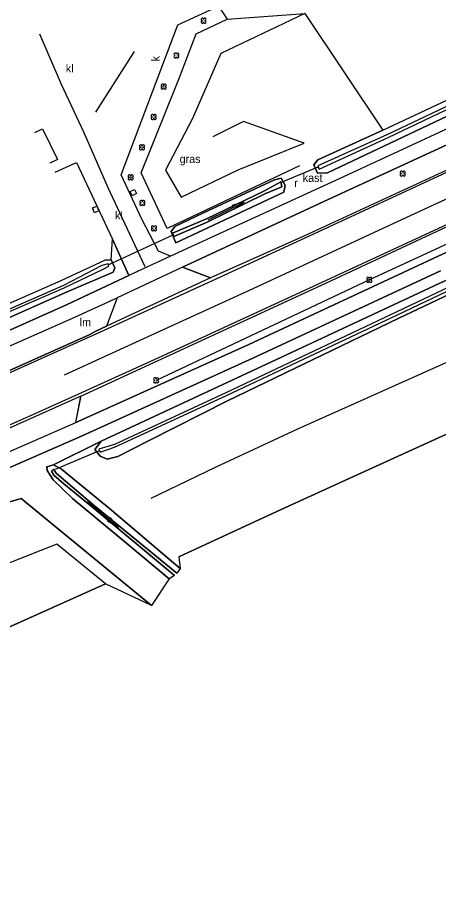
# Model space of a CAD drawing. Extents: x 154825 to 158680, y 370717 to 378075.
# Drawn here: x 157115 to 157167.5, y 372493.5 to 372604 of the extents above; entities that cross this region are included whole.
import ezdxf

# ---------------------------------------------------------------- set-up
doc = ezdxf.new("R2010")
doc.units = 0
for name, color, linetype in [('boom', 7, 'Continuous'), ('breuklijn', 7, 'Continuous'), ('cultuurscheiding', 7, 'Continuous'), ('deelstreep(3-9)', 7, 'Continuous'), ('duiker lijn', 7, 'Continuous'), ('grazige vegetatie(vs)', 7, 'Continuous'), ('hoogteverschillijn', 7, 'Continuous'), ('insteek sloot', 7, 'Continuous'), ('kantstreep', 7, 'Continuous'), ('kast_huis punt', 7, 'Continuous'), ('klinkerverharding(vs)', 7, 'Continuous'), ('kolk', 7, 'Continuous'), ('maaiveldlijn algemeen - gesloten verharding', 7, 'Continuous'), ('maaiveldlijn algemeen - muur', 7, 'Continuous'), ('maaiveldlijn algemeen - open verharding', 7, 'Continuous'), ('maaiveldlijn algemeen - verharding algemeen', 7, 'Continuous'), ('raster - hek', 7, 'Continuous'), ('rioolput(z_inl)', 7, 'Continuous'), ('Sloot bodem', 7, 'Continuous'), ('stroomrichting  watergangen', 7, 'Continuous'), ('verlichtingsobject', 7, 'Continuous'), ('vlak_Grasland', 7, 'Continuous'), ('vlak_Grazige_vegetatie', 7, 'Continuous')]:
    doc.layers.add(name, color=color, linetype=linetype)

msp = doc.modelspace()

# ---------------------------------------------------------------- linework, layer by layer
at = {"layer": 'boom'}
msp.add_lwpolyline([(157213.98, 372596.85), (157185.75, 372583.62), (157158.89, 372571.23), (157132.29, 372558.67)], dxfattribs=at)
for centre in [(157138.2, 372603.6), (157134.82, 372599.25), (157133.23, 372595.37), (157131.99, 372591.57), (157130.53, 372587.79), (157163.06, 372584.5), (157129.11, 372584.04), (157130.58, 372580.84), (157132.01, 372577.65), (157158.89, 372571.23), (157132.29, 372558.67)]:
    msp.add_circle(centre, 0.006, dxfattribs=at)
for centre, start, end in [((157138.05, 372603.76), 357.075, 272.925), ((157138.05, 372603.44), 87.075, 2.925), ((157138.36, 372603.76), 267.075, 182.925), ((157138.36, 372603.44), 177.075, 92.925), ((157134.67, 372599.41), 357.075, 272.925), ((157134.67, 372599.1), 87.075, 2.925), ((157134.98, 372599.41), 267.075, 182.925), ((157134.98, 372599.1), 177.075, 92.925), ((157133.07, 372595.53), 357.075, 272.925), ((157133.39, 372595.53), 267.075, 182.925), ((157133.07, 372595.22), 87.075, 2.925), ((157133.39, 372595.22), 177.075, 92.925), ((157131.83, 372591.73), 357.075, 272.925), ((157131.83, 372591.41), 87.075, 2.925), ((157132.15, 372591.73), 267.075, 182.925), ((157132.15, 372591.41), 177.075, 92.925), ((157130.37, 372587.95), 357.075, 272.925), ((157130.37, 372587.63), 87.075, 2.925), ((157130.69, 372587.95), 267.075, 182.925), ((157130.69, 372587.63), 177.075, 92.925), ((157162.9, 372584.66), 357.075, 272.925), ((157162.9, 372584.35), 87.075, 2.925), ((157163.22, 372584.66), 267.075, 182.925), ((157163.22, 372584.35), 177.075, 92.925), ((157128.95, 372584.2), 357.075, 272.925), ((157128.95, 372583.88), 87.075, 2.925), ((157129.27, 372584.2), 267.075, 182.925), ((157129.27, 372583.88), 177.075, 92.925), ((157130.42, 372581), 357.075, 272.925), ((157130.74, 372581), 267.075, 182.925), ((157130.42, 372580.69), 87.075, 2.925), ((157130.74, 372580.69), 177.075, 92.925), ((157131.85, 372577.81), 357.075, 272.925), ((157132.17, 372577.81), 267.075, 182.925), ((157131.85, 372577.5), 87.075, 2.925), ((157132.17, 372577.5), 177.075, 92.925), ((157158.73, 372571.39), 357.075, 272.925), ((157158.73, 372571.07), 87.075, 2.925), ((157159.04, 372571.39), 267.075, 182.925), ((157159.04, 372571.07), 177.075, 92.925), ((157132.13, 372558.83), 357.075, 272.925), ((157132.45, 372558.83), 267.075, 182.925), ((157132.13, 372558.51), 87.075, 2.925), ((157132.45, 372558.51), 177.075, 92.925)]:
    msp.add_arc(centre, 0.158, start, end, dxfattribs=at)
at = {"layer": 'breuklijn'}
for points in [[(157150.85, 372604.52), (157140.35, 372599.51), (157136.84, 372591.39), (157133.44, 372584.94), (157135.43, 372581.56), (157142.54, 372584.96), (157150.75, 372588.29), (157143.18, 372591.01), (157139.36, 372589.08)], [(157130.9, 372572.86), (157129, 372576.93), (157126.3, 372582.74), (157123.3, 372589.58), (157120.49, 372595.62), (157117.77, 372601.91)], [(157124.77, 372592.16), (157129.61, 372599.76)]]:
    msp.add_lwpolyline(points, dxfattribs=at)
at = {"layer": 'cultuurscheiding'}
msp.add_lwpolyline([(157119.47, 372548.1), (157125.41, 372551.06)], dxfattribs=at)
at = {"layer": 'deelstreep(3-9)'}
msp.add_lwpolyline([(157308.93, 372646.58), (157285.67, 372635.73), (157262.56, 372625), (157240.8, 372614.9), (157229.89, 372609.83), (157208.16, 372599.73), (157197.28, 372594.69), (157176.47, 372584.99), (157165.79, 372580.07), (157144.37, 372570.1), (157131.72, 372564.33), (157120.8, 372559.34)], dxfattribs=at)
at = {"layer": 'duiker lijn'}
for points in [[(157152.48, 372585.32), (157147.88, 372583.4)], [(157126.32, 372573.1), (157134.4, 372576.86)], [(157125.11, 372549.83), (157119.7, 372547.53)]]:
    msp.add_lwpolyline(points, dxfattribs=at)
at = {"layer": 'hoogteverschillijn'}
for points in [[(157135.14, 372536.64), (157147.33, 372542.3), (157157.39, 372546.88), (157174.01, 372554.44), (157182.06, 372557.76), (157199.41, 372565.5), (157207.14, 372569.14), (157217.33, 372573.59), (157225.17, 372577.25), (157220.34, 372585.21), (157210.16, 372580.28), (157199.1, 372574.84), (157186.14, 372569.77), (157176.77, 372565.02), (157169.17, 372561.19), (157149.94, 372552.57), (157139.65, 372547.77), (157131.61, 372543.92)], [(157026.21, 372507.77), (157038.05, 372493.47), (157053.84, 372500.41), (157064.32, 372505.29), (157082.04, 372513.73), (157099.19, 372521.06), (157114.22, 372527.96), (157125.97, 372533.26), (157119.9, 372538.21), (157106.1, 372532.74), (157095.12, 372527.24), (157084.64, 372522.61), (157073.6, 372517.88), (157061.99, 372513.42), (157050.38, 372508.13), (157038.81, 372503.28)]]:
    msp.add_lwpolyline(points, dxfattribs=at)
at = {"layer": 'insteek sloot'}
for points in [[(157185.03, 372601.76), (157185.99, 372601.72), (157186.54, 372600.97), (157186.51, 372600.12), (157184.6, 372599.14), (157168.61, 372591.68), (157153.67, 372584.61), (157152.41, 372584.57), (157151.95, 372585.58), (157152.47, 372586.22), (157160.56, 372589.94), (157178.13, 372598.16), (157185.03, 372601.76)], [(157125.41, 372551.06), (157144.82, 372560.12), (157168.23, 372571.06), (157192.15, 372582.14), (157214.33, 372592.42), (157231.51, 372600.35)], [(157229.49, 372575.59), (157223.27, 372585.02), (157219.29, 372591.66), (157218.52, 372591.88), (157205.82, 372586.39), (157183.29, 372576.28), (157162.59, 372566.44), (157141.18, 372556.1), (157131.42, 372551.16), (157127.51, 372549.15), (157126.18, 372548.81), (157125.29, 372549.21), (157124.66, 372550.05), (157125.41, 372551.06)], [(157147.04, 372583.73), (157147.87, 372583.94), (157148.37, 372583.02), (157148.23, 372582.18), (157134.76, 372575.84), (157134.63, 372576.16), (157134.15, 372577.27), (157134.64, 372577.88), (157138.1, 372579.57), (157147.04, 372583.73)], [(157108.06, 372566.2), (157109.34, 372566.26), (157120.45, 372571.14), (157125.98, 372573.72), (157126.66, 372573.71), (157127.14, 372572.72), (157126.93, 372572.17), (157120.88, 372569.62), (157108.26, 372564), (157096.05, 372558.59), (157082.53, 372552.97), (157070.93, 372548.12), (157053.32, 372541.26), (157038.38, 372535.36), (157020.77, 372528.28), (157013.25, 372525.44), (157009.25, 372524.08)], [(157133.93, 372533.88), (157128.63, 372538.31), (157121.87, 372543.93), (157119.44, 372546.24), (157118.68, 372547.42), (157118.65, 372547.86), (157119.47, 372548.1)], [(157119.47, 372548.1), (157120.5, 372547.57), (157126.45, 372542.68), (157135.3, 372535.16)]]:
    msp.add_lwpolyline(points, dxfattribs=at)
at = {"layer": 'kantstreep'}
for points in [[(157311.2, 372650.93), (157292.95, 372642.43), (157267.24, 372630.47), (157245.28, 372620.26), (157218.06, 372607.61), (157194.71, 372596.77), (157169.7, 372585.19), (157150.86, 372576.45), (157139.72, 372571.31), (157125.21, 372564.64), (157109.64, 372557.65), (157098.21, 372552.78), (157087.26, 372548.23), (157074.29, 372542.96), (157049.86, 372533.16), (157026.89, 372524.04), (157012.16, 372518.48), (156991.58, 372511.62)], [(157175.88, 372581.53), (157152.95, 372570.91), (157132.6, 372561.49), (157122.61, 372556.94), (157115.96, 372553.95), (157107.38, 372550.18), (157099.77, 372546.99), (157087.24, 372541.81), (157074.56, 372536.7), (157059.91, 372530.81), (157042.11, 372523.71), (157012.96, 372512.06), (157003.79, 372508.51)]]:
    msp.add_lwpolyline(points, dxfattribs=at)
at = {"layer": 'maaiveldlijn algemeen - gesloten verharding'}
for points in [[(157322.19, 372661.35), (157315.02, 372658), (157308.87, 372655.13), (157283.28, 372643.29), (157259.58, 372632.3), (157235.97, 372621.56), (157212.56, 372610.51), (157191.51, 372600.67), (157169.85, 372590.67), (157155.14, 372583.86), (157134.07, 372574.17)], [(157122.91, 372556.7), (157132.56, 372561.17), (157152.93, 372570.58), (157176.01, 372581.34), (157200.28, 372592.63), (157225.35, 372604.23), (157226.76, 372604.76), (157235.03, 372608.61)], [(157110.82, 372548.4), (157122.28, 372553.42), (157143.85, 372563.14), (157166.86, 372573.91), (157191.27, 372585.24), (157213.36, 372595.47), (157229.94, 372603.18)], [(157188.29, 372597.29), (157170.71, 372589.1), (157153.74, 372581.26), (157135.57, 372572.82)], [(157188.24, 372594.03), (157169.63, 372585.45), (157150.71, 372576.68), (157139.08, 372571.47)], [(157134.07, 372574.17), (157128.9, 372571.78)], [(157167.76, 372572.35), (157144.36, 372561.46), (157123.04, 372551.73), (157111.7, 372546.79), (157102.57, 372542.8), (157088.59, 372537.06), (157075.48, 372531.64), (157054.14, 372523.12), (157031.09, 372514.01), (157015.05, 372507.58), (157011.92, 372506.3)], [(157135.57, 372572.82), (157127.42, 372568.97)], [(157014.85, 372524.67), (157021.19, 372527.06), (157042.56, 372535.57), (157056.69, 372541.2), (157071.28, 372547.08), (157083.31, 372551.8), (157096.41, 372557.27), (157107.37, 372561.97), (157121.17, 372568.15), (157128.9, 372571.78)], [(157139.08, 372571.47), (157126.09, 372565.46)], [(157015.48, 372522.82), (157021.03, 372525.08), (157044.1, 372534.25), (157062.4, 372541.48), (157072.01, 372545.27), (157084.31, 372550.26), (157097.21, 372555.57), (157108.07, 372560.35), (157121.78, 372566.39), (157127.42, 372568.97)], [(156922.46, 372501.17), (156931.02, 372501.52), (156941.73, 372502.29), (156951.69, 372503.24), (156968.73, 372506.03), (156976.2, 372507.57), (156991.56, 372512.01), (157005.71, 372516.48), (157024.46, 372523.39), (157049.88, 372533.46), (157074.19, 372543.22), (157087.19, 372548.51), (157098.23, 372553.06), (157109.59, 372557.96), (157123.94, 372564.35), (157124.86, 372564.87), (157126.09, 372565.46)], [(157011.64, 372511.26), (157012.98, 372511.83), (157021.25, 372515.12), (157042.23, 372523.46), (157060.04, 372530.55), (157076.74, 372537.25), (157087.3, 372541.54), (157099.91, 372546.74), (157107.54, 372550.01), (157108.5, 372550.29), (157122.92, 372556.72)]]:
    msp.add_lwpolyline(points, dxfattribs=at)
at = {"layer": 'maaiveldlijn algemeen - muur'}
for points in [[(157129.28, 372581.74), (157129.03, 372582.27), (157129.58, 372582.52), (157129.82, 372582), (157129.28, 372581.74)], [(157124.88, 372580.45), (157125.13, 372579.86), (157124.58, 372579.62), (157124.33, 372580.22), (157124.88, 372580.45)]]:
    msp.add_lwpolyline(points, dxfattribs=at)
at = {"layer": 'maaiveldlijn algemeen - open verharding'}
for points in [[(157134.07, 372574.17), (157132.58, 372574.82), (157130.51, 372578.83)], [(157128.9, 372571.78), (157126.85, 372576.3)], [(157135.57, 372572.82), (157139.08, 372571.47)], [(157127.42, 372568.97), (157126.09, 372565.46)], [(157122.26, 372553.41), (157122.92, 372556.72)]]:
    msp.add_lwpolyline(points, dxfattribs=at)
at = {"layer": 'maaiveldlijn algemeen - verharding algemeen'}
for points in [[(157130.51, 372578.83), (157127.94, 372584.36), (157131.27, 372593.19), (157134.99, 372603.08), (157140.08, 372605.41)], [(157117.14, 372589.63), (157118.12, 372590.1), (157119.97, 372586.27), (157119.02, 372585.82)], [(157119.68, 372584.67), (157122.34, 372585.89), (157124.88, 372580.47), (157126.85, 372576.3)]]:
    msp.add_lwpolyline(points, dxfattribs=at)
at = {"layer": 'raster - hek'}
for points in [[(157150.18, 372585.49), (157133.67, 372577.66), (157130.44, 372584.58), (157135.11, 372596.28), (157137.27, 372601.97), (157141.17, 372603.79)], [(157131.69, 372530.53), (157120.12, 372540.09), (157115.45, 372543.92), (157113.73, 372543.4)]]:
    msp.add_lwpolyline(points, dxfattribs=at)
at = {"layer": 'Sloot bodem'}
for points in [[(157152.47, 372585.47), (157152.65, 372585.06), (157161.25, 372589.03), (157179.03, 372597.5), (157186.26, 372600.73), (157185.99, 372601.37), (157178.87, 372597.8), (157161.06, 372589.35), (157152.47, 372585.47)], [(157134.49, 372576.65), (157134.32, 372577.06), (157138.57, 372578.86), (157145.74, 372582.32), (157147.85, 372583.47), (157147.99, 372582.84), (157145.87, 372581.96), (157138.67, 372578.45), (157134.49, 372576.65)], [(157183.7, 372577.38), (157162.33, 372567.25), (157140.98, 372557.1), (157127.08, 372550.68), (157125.12, 372550.09), (157125.31, 372549.71), (157127.11, 372550.33), (157141.05, 372556.8), (157162.5, 372566.9), (157183.84, 372577.06)], [(157009.51, 372524.52), (157015.89, 372526.9), (157036.06, 372534.88), (157052.6, 372541.57), (157070.42, 372548.8), (157082.2, 372553.44), (157095.73, 372559.13), (157108.28, 372564.8), (157120.83, 372570.23), (157125.69, 372572.57), (157126.4, 372572.92), (157126.29, 372573.25), (157125.51, 372573.03), (157120.75, 372570.54), (157108.26, 372565.06), (157095.6, 372559.45), (157082.09, 372553.71), (157070.24, 372549.26), (157052.53, 372541.89), (157035.02, 372534.84), (157019.64, 372528.67)], [(157134.59, 372534.29), (157124.39, 372542.77), (157120.78, 372545.76), (157119.53, 372546.82), (157119.22, 372547.31), (157119.48, 372547.56), (157119.82, 372547.09), (157120.98, 372546.1), (157124.61, 372542.98), (157134.88, 372534.58)]]:
    msp.add_lwpolyline(points, dxfattribs=at)
at = {"layer": 'stroomrichting  watergangen'}
for p, q in [((157138.79, 372578.73), (157143.26, 372580.94)), ((157143.24, 372580.95), (157141.73, 372580.5)), ((157143.26, 372580.94), (157141.99, 372580)), ((157123.74, 372543.5), (157127.58, 372540.31)), ((157127.58, 372540.33), (157126.56, 372541.54)), ((157127.58, 372540.31), (157126.21, 372541.09))]:
    msp.add_line(p, q, dxfattribs=at)
at = {"layer": 'vlak_Grasland'}
msp.add_lwpolyline([(157174.01, 372554.44), (157157.39, 372546.88), (157147.33, 372542.3), (157135.14, 372536.64), (157135.3, 372535.16), (157126.45, 372542.68), (157120.5, 372547.57), (157119.47, 372548.1), (157125.41, 372551.06), (157124.66, 372550.05), (157125.29, 372549.21), (157126.18, 372548.81), (157127.51, 372549.15), (157131.42, 372551.16), (157141.18, 372556.1), (157162.59, 372566.44), (157183.29, 372576.28)], dxfattribs=at)
msp.add_lwpolyline([(157120.12, 372540.09), (157131.69, 372530.53), (157125.97, 372533.26), (157114.22, 372527.96), (157099.19, 372521.06), (157082.04, 372513.73), (157064.32, 372505.29), (157053.84, 372500.41), (157038.05, 372493.47), (157026.21, 372507.77), (157018.14, 372505.41), (157031.94, 372510.94), (157054.85, 372519.98), (157077.26, 372528.94), (157089.42, 372533.74), (157104.3, 372539.6), (157113.73, 372543.4), (157115.45, 372543.92)], close=True, dxfattribs=at)
at = {"layer": 'vlak_Grazige_vegetatie'}
for points in [[(157169.85, 372590.67), (157155.14, 372583.86), (157134.07, 372574.17), (157132.58, 372574.82), (157130.51, 372578.83), (157127.94, 372584.36), (157131.27, 372593.19), (157134.99, 372603.08), (157140.08, 372605.41), (157141.17, 372603.79), (157150.85, 372604.52), (157160.56, 372589.94), (157152.47, 372586.22), (157151.95, 372585.58), (157152.41, 372584.57), (157153.67, 372584.61), (157168.61, 372591.68)], [(157183.7, 372577.38), (157162.33, 372567.25), (157140.98, 372557.1), (157127.08, 372550.68), (157125.12, 372550.09), (157125.31, 372549.71), (157127.11, 372550.33), (157141.05, 372556.8), (157162.5, 372566.9), (157183.84, 372577.06)], [(157108.26, 372564), (157120.88, 372569.62), (157126.93, 372572.17), (157127.14, 372572.72), (157126.66, 372573.71), (157126.85, 372576.3), (157128.9, 372571.78), (157121.17, 372568.15), (157107.37, 372561.97)], [(157183.29, 372576.28), (157162.59, 372566.44), (157141.18, 372556.1), (157131.42, 372551.16), (157127.51, 372549.15), (157126.18, 372548.81), (157125.29, 372549.21), (157124.66, 372550.05), (157125.41, 372551.06), (157144.82, 372560.12), (157168.23, 372571.06)], [(157009.49, 372525.77), (157019.28, 372529.69), (157049.38, 372541.31), (157070.08, 372550.38), (157071.63, 372550.62), (157081.51, 372554.36), (157095.52, 372560.35), (157108.06, 372566.2), (157109.34, 372566.26), (157120.45, 372571.14), (157125.98, 372573.72), (157126.66, 372573.71), (157127.14, 372572.72), (157126.93, 372572.17), (157120.88, 372569.62), (157108.26, 372564), (157096.05, 372558.59), (157082.53, 372552.97), (157070.93, 372548.12), (157053.32, 372541.26), (157038.38, 372535.36), (157020.77, 372528.28), (157013.25, 372525.44), (157009.25, 372524.08)], [(157009.51, 372524.52), (157015.89, 372526.9), (157036.06, 372534.88), (157052.6, 372541.57), (157070.42, 372548.8), (157082.2, 372553.44), (157095.73, 372559.13), (157108.28, 372564.8), (157120.83, 372570.23), (157125.69, 372572.57), (157126.4, 372572.92), (157126.29, 372573.25), (157125.51, 372573.03), (157120.75, 372570.54), (157108.26, 372565.06), (157095.6, 372559.45), (157082.09, 372553.71), (157070.24, 372549.26), (157052.53, 372541.89), (157035.02, 372534.84), (157019.64, 372528.67), (157013.88, 372526.47), (157007.54, 372524.25)], [(157111.7, 372546.79), (157123.04, 372551.73), (157144.36, 372561.46), (157167.76, 372572.35)], [(157168.23, 372571.06), (157144.82, 372560.12), (157125.41, 372551.06), (157119.47, 372548.1), (157118.65, 372547.86), (157118.68, 372547.42), (157119.44, 372546.24), (157121.87, 372543.93), (157128.63, 372538.31), (157133.93, 372533.88), (157131.69, 372530.53), (157120.12, 372540.09), (157115.45, 372543.92), (157113.73, 372543.4)], [(157001.42, 372518.14), (157010.95, 372521.09), (157015.48, 372522.82), (157021.03, 372525.08), (157044.1, 372534.25), (157062.4, 372541.48), (157072.01, 372545.27), (157084.31, 372550.26), (157097.21, 372555.57), (157108.07, 372560.35), (157121.78, 372566.39), (157127.42, 372568.97), (157126.09, 372565.46), (157124.86, 372564.87), (157123.94, 372564.35), (157109.59, 372557.96), (157098.23, 372553.06), (157087.19, 372548.51), (157074.19, 372543.22), (157049.88, 372533.46), (157024.46, 372523.39), (157005.71, 372516.48)]]:
    msp.add_lwpolyline(points, dxfattribs=at)
for points in [[(157143.85, 372563.14), (157122.28, 372553.42), (157122.91, 372556.7), (157132.56, 372561.17), (157152.93, 372570.58), (157176.01, 372581.34), (157200.28, 372592.63), (157225.35, 372604.23), (157226.76, 372604.76), (157229.94, 372603.18), (157213.36, 372595.47), (157191.27, 372585.24), (157166.86, 372573.91)], [(157185.99, 372601.72), (157186.54, 372600.97), (157186.51, 372600.12), (157184.6, 372599.14), (157168.61, 372591.68), (157153.67, 372584.61), (157152.41, 372584.57), (157151.95, 372585.58), (157152.47, 372586.22), (157160.56, 372589.94), (157178.13, 372598.16), (157185.03, 372601.76)], [(157152.47, 372585.47), (157152.65, 372585.06), (157161.25, 372589.03), (157179.03, 372597.5), (157186.26, 372600.73), (157185.99, 372601.37), (157178.87, 372597.8), (157161.06, 372589.35)], [(157150.71, 372576.68), (157139.08, 372571.47), (157135.57, 372572.82), (157153.74, 372581.26), (157170.71, 372589.1), (157188.29, 372597.29), (157188.24, 372594.03), (157169.63, 372585.45)], [(157134.63, 372576.16), (157134.76, 372575.84), (157148.23, 372582.18), (157148.37, 372583.02), (157147.87, 372583.94), (157147.04, 372583.73), (157138.1, 372579.57), (157134.64, 372577.88), (157134.15, 372577.27)], [(157147.87, 372583.94), (157148.37, 372583.02), (157148.23, 372582.18), (157134.76, 372575.84), (157134.63, 372576.16), (157134.15, 372577.27), (157134.64, 372577.88), (157138.1, 372579.57), (157147.04, 372583.73)], [(157134.32, 372577.06), (157134.49, 372576.65), (157138.67, 372578.45), (157145.87, 372581.96), (157147.99, 372582.84), (157147.85, 372583.47), (157145.74, 372582.32), (157138.57, 372578.86)], [(157120.5, 372547.57), (157126.45, 372542.68), (157135.3, 372535.16), (157134.88, 372534.58), (157124.61, 372542.98), (157120.98, 372546.1), (157119.82, 372547.09), (157119.48, 372547.56), (157119.22, 372547.31), (157119.53, 372546.82), (157120.78, 372545.76), (157124.39, 372542.77), (157134.59, 372534.29), (157133.93, 372533.88), (157128.63, 372538.31), (157121.87, 372543.93), (157119.44, 372546.24), (157118.68, 372547.42), (157118.65, 372547.86), (157119.47, 372548.1)]]:
    msp.add_lwpolyline(points, close=True, dxfattribs=at)

# ---------------------------------------------------------------- texts
at = {"layer": 'grazige vegetatie(vs)'}
msp.add_text('gras', height=1, dxfattribs=at).set_placement((157135.22, 372585.83))
at = {"layer": 'kast_huis punt'}
msp.add_text('kast', height=1, dxfattribs=at).set_placement((157150.58, 372583.47))
at = {"layer": 'klinkerverharding(vs)'}
for p in [(157121.02, 372597.15), (157127.17, 372578.78)]:
    msp.add_text('kl', height=1, dxfattribs=at).set_placement(p)
at = {"layer": 'kolk'}
msp.add_text('k', height=1, rotation=90, dxfattribs=at).set_placement((157132.71, 372598.51))
at = {"layer": 'rioolput(z_inl)'}
msp.add_text('r', height=1, dxfattribs=at).set_placement((157149.52, 372582.83))
at = {"layer": 'verlichtingsobject'}
msp.add_text('lm', height=1, dxfattribs=at).set_placement((157122.76, 372565.44))

doc.saveas('drawing.dxf')
